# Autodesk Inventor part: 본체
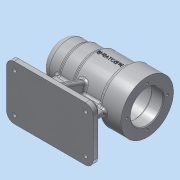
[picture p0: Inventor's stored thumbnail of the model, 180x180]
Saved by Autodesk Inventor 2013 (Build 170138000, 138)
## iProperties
Created: 2016-06
Part Number: 본체
Material: 알루미늄 6061
Document SubType Name: Modeling
Designer: Administrator
Density: 2.71 g/cm^3
Mass: 673.897 g
Surface Area: 647.23 cm^2
Volume: 248.671 cm^3
Author: Administrator
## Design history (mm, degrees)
sketch "스케치1"
  geometry: L1 (-112, 0)-(-112, 25); L2 (-112, 25)-(-87, 25); L3 (-87, 25)-(-87, 27); L4 (-87, 27)-(-67, 27); L5 (-67, 27)-(-67, 30); L6 (-67, 30)-(-28, 30); L7 (-28, 30)-(-28, 34); L8 (-28, 34)-(0, 34); L9 (0, 34)-(0, 0); L10 (0, 0)-(-112, 0)
  constraints: 20 end point, 8 parallel, 1 perpendicular, 1 vertical
  dimensions: "d0" = 50 diameter of L2 L10; "d2" = 54 diameter of L4 L10; "d3" = 60 diameter of L6 L10; "d4" = 68 diameter of L8 L10; "d5" = 25 distance of L1.end L2.end; "d6" = 45 distance between parallel lines of L5 L1; "d7" = 84 distance between parallel lines of L7 L1; "d8" = 112 distance between parallel lines of L9 L1
revolve "회전1" sketch "스케치1" stored, may be unused: angle "d9" = 90 deg
fillet "모깎기1" dims "d10" = 10
fillet "모깎기2" dims "d11" = 3
sketch "스케치2"
  geometry: L1 (-35, -60)-(35, -60); L2 (35, -60)-(35, -70); L3 (35, -70)-(-35, -70); L4 (-35, -70)-(-35, -60); C1 r 34 at (0, 0) reference; 1 further point
  constraints: 8 end point, 2 parallel, 1 horizontal, 1 midpoint, 1 perpendicular, 1 vertical alignment
  dimensions: "d12" = 10 distance of L3.end L1.start; "d14" = 70 distance from line of C1.centre L3; "d15" = 70 distance of L2.end L3.end
extrude "돌출1" join sketch "스케치2" distance "d16" = 112; taper "d17" = 0 deg
sketch "스케치3"
  geometry: L1 (-31, -30)-(-64.804, -30) reference; L2 (-70, -27)-(-85.356, -27) reference; L3 (-89.828, -25)-(-102, -25) reference; L4 (-112, -15)-(-112, 15) reference; L5 (-102, 25)-(-89.828, 25) reference; L6 (-85.356, 27)-(-70, 27) reference; L7 (-64.804, 30)-(-31, 30) reference; L8 (-25.343, 34)-(0, 34) reference; L9 (0, 34)-(0, -34) reference; L10 (0, -34)-(-25.343, -34) reference; L11 (-112, -60)-(0, -60) reference; L12 (0, -60)-(0, -70) reference; L13 (0, -70)-(-112, -70) reference; L14 (-112, -70)-(-112, -60) reference; L15 (-92, -60)-(-92, 0); L16 (-20, -60)-(-20, 0); L17 (-92, 0)-(-20, 0); A1 r 3 centre (-25.343, -31) between (-28.172, -32) and (-25.343, -34) reference; A2 r 3 centre (-31, -33) between (-28.172, -32) and (-31, -30) reference; A3 r 3 centre (-64.804, -27) between (-67.402, -28.5) and (-64.804, -30) reference; A4 r 3 centre (-70, -30) between (-67.402, -28.5) and (-70, -27) reference; A5 r 3 centre (-85.356, -24) between (-87.592, -26) and (-85.356, -27) reference; A6 r 3 centre (-89.828, -28) between (-87.592, -26) and (-89.828, -25) reference; A7 r 10 centre (-102, -15) between (-112, -15) and (-102, -25) reference; A8 r 10 centre (-102, 15) between (-102, 25) and (-112, 15) reference; A9 r 3 centre (-89.828, 28) between (-89.828, 25) and (-87.592, 26) reference; A10 r 3 centre (-85.356, 24) between (-85.356, 27) and (-87.592, 26) reference; A11 r 3 centre (-70, 30) between (-70, 27) and (-67.402, 28.5) reference; A12 r 3 centre (-64.804, 27) between (-64.804, 30) and (-67.402, 28.5) reference; A13 r 3 centre (-31, 33) between (-31, 30) and (-28.172, 32) reference; A14 r 3 centre (-25.343, 31) between (-25.343, 34) and (-28.172, 32) reference; 2 further points
  constraints: 6 end point, 2 parallel, 2 point on line, 1 horizontal alignment, 1 midpoint, 1 perpendicular
  dimensions: "d18" = 20 distance between parallel lines of L12 L16; "d19" = 20 distance between parallel lines of L14 L15
extrude "돌출2" join sketch "스케치3" stored distance "d20" = 8; taper "d21" = 0 deg
node "작업 평면1"
sketch "스케치4"
  geometry: L1 (-35, -70)-(-35, -60) reference; L2 (-35, -60)-(-4, -60) reference; L3 (-4, -60)-(-4, -29.732) reference; L4 (4, -29.732)-(4, -60) reference; L5 (4, -60)-(35, -60) reference; L6 (35, -60)-(35, -70) reference; L7 (35, -70)-(-35, -70) reference; L8 (28, -60)-(6.162, 0); L9 (-28, -60)-(-6.162, 0); L10 (-6.162, 0)-(6.162, 0); A1 r 30 centre (0, 0) between (4, -29.732) and (-4, -29.732) reference; 1 further point
  constraints: 6 end point, 2 horizontal alignment, 2 point on line, 1 parallel
  dimensions: "d23" = 110 deg angle of L5 L8; "d24" = 110 deg angle of L2 L9; "d25" = 7 distance from line of L9.start L1; "d26" = 7 distance from line of L6 L8.start
extrude "돌출3" join sketch "스케치4" stored distance "d27" = 8; taper "d28" = 0 deg
sketch "스케치5"
  geometry: L1 (0, 26)-(0, -26); L2 (-26, 0)-(26, 0); C1 r 34 at (0, 0) reference; 5 further points
  constraints: 5 coincident, 4 end point, 2 midpoint, 2 perpendicular, 1 vertical
  dimensions: "d29" = 52 distance of L2.start L2.end
hole "구멍1" sketch "스케치5" at (0, 26), (-26, 0), (0, -26), (26, 0) diameter "d31" = 3.242; stored, may be unused: countersink angle "d35" = 90 deg, drill point angle "d37" = 118 deg; dims "d32" = 8, "d33" = 4, "d34" = 2, "d36" = 11
sketch "스케치6"
  geometry: L1 (0, 70)-(-112, 70) reference; L2 (-112, 0)-(-112, 70) reference; L3 (-102, 60)-(-10, 60); L4 (-10, 60)-(-10, 10); L5 (-10, 10)-(-102, 10); L6 (-102, 10)-(-102, 60); 9 further points
  constraints: 8 end point, 4 coincident, 4 midpoint, 2 parallel, 1 horizontal, 1 horizontal alignment, 1 perpendicular, 1 vertical alignment
  dimensions: "d38" = 92 distance of L4.end L5.end; "d40" = 50 distance of L5.end L3.start
hole "구멍2" sketch "스케치6" at (-102, 60), (-10, 60), (-102, 10), (-10, 10) diameter "d41" = 5; stored, may be unused: countersink angle "d45" = 90 deg, drill point angle "d47" = 118 deg; dims "d42" = 5, "d43" = 9, "d44" = 4, "d46" = 11
node "작업 평면2"
sketch "스케치7"
  geometry: L1 (0, -34)-(0, 34) reference; 3 further points
  constraints: 1 horizontal alignment, 1 midpoint, 1 other
  dimensions: "d49" = 48 distance from line of L1 point (-48, 0)
feature "엠보싱1" sketch "스케치7" dims "d50" = 0.5, "d51" = 0
fillet "모깎기3" dims "d52" = 10
sketch "스케치8"
  geometry: L1 (-25.343, 34)-(0, 34) reference; L2 (0, 34)-(0, 27.621) reference; L3 (0, 27.621)-(-11, 27.621) reference; L4 (-11, 27.621)-(-11.974, 26) reference; L5 (-11.974, 26)-(-11, 24.379) reference; L6 (-11, 24.379)-(0, 24.379) reference; L7 (0, 24.379)-(0, -24.379) reference; L8 (0, -24.379)-(-11, -24.379) reference; L9 (-11, -24.379)-(-11.974, -26) reference; L10 (-11.974, -26)-(-11, -27.621) reference; L11 (-11, -27.621)-(0, -27.621) reference; L12 (0, -27.621)-(0, -34) reference; L13 (0, -34)-(-20, -34) reference; L14 (-20, -34)-(-20, -60) reference; L15 (-20, -60)-(0, -60) reference; L16 (0, -60)-(0, -70) reference; L17 (0, -70)-(-112, -70) reference; L18 (-112, -70)-(-112, -60) reference; L19 (-112, -60)-(-92, -60) reference; L20 (-92, -60)-(-92, -25) reference; L21 (-92, -25)-(-102, -25) reference; L22 (-112, -15)-(-112, 15) reference; L23 (-102, 25)-(-89.828, 25) reference; L24 (-85.356, 27)-(-70, 27) reference; L25 (-64.804, 30)-(-31, 30) reference; L26 (-106, 0)-(-106, 10.5); L27 (-106, 10.5)-(-103, 10.5); L28 (-103, 10.5)-(-103, 16); L29 (-103, 16)-(-99, 16); L30 (-99, 16)-(-99, 17.5); L31 (-99, 17.5)-(-81, 17.5); L32 (-81, 17.5)-(-81, 21); L33 (-81, 21)-(-69, 21); L34 (-69, 21)-(-69, 24); L35 (-69, 24)-(-15, 24); L36 (-15, 24)-(-15, 21); L37 (-15, 21)-(0, 21); L38 (-106, 0)-(0, 0); A1 r 3 centre (-25.343, 31) between (-25.343, 34) and (-28.172, 32) reference; A2 r 10 centre (-102, -15) between (-112, -15) and (-102, -25) reference; A3 r 10 centre (-102, 15) between (-102, 25) and (-112, 15) reference; A4 r 3 centre (-89.828, 28) between (-89.828, 25) and (-87.592, 26) reference; A5 r 3 centre (-85.356, 24) between (-85.356, 27) and (-87.592, 26) reference; A6 r 3 centre (-70, 30) between (-70, 27) and (-67.402, 28.5) reference; A7 r 3 centre (-64.804, 27) between (-64.804, 30) and (-67.402, 28.5) reference; A8 r 3 centre (-31, 33) between (-31, 30) and (-28.172, 32) reference
  constraints: 26 end point, 8 parallel, 5 perpendicular, 1 point on line
  dimensions: "d53" = 3 distance of L26.end L27.end; "d55" = 4 distance of L28.end L29.end; "d56" = 18 distance of L30.end L31.end; "d57" = 12 distance of L32.end L33.end; "d58" = 54 distance of L34.end L35.end; "d59" = 15 distance of L36.end L37.end; "d60" = 42 diameter of L37 L38; "d61" = 48 diameter of L35 L38; "d62" = 42 diameter of L33 L38; "d63" = 35 diameter of L31 L38; "d64" = 32 diameter of L29 L38; "d65" = 21 diameter of L27 L38
revolve "회전2" sketch "스케치8" stored, may be unused: angle "d66" = 90 deg
fillet "모깎기4" dims "d67" = 3
fillet "모깎기5" dims "d68" = 0.3
fillet "모깎기6" dims "d69" = 3
chamfer "모따기1" distance "d70" = 1; stored, may be unused: second distance "d71" = 2, angle "d72" = 45 deg
fillet "모깎기7" dims "d73" = 3
fillet "모깎기9" dims "d75" = 3
chamfer "모따기2" distance "d76" = 4; stored, may be unused: second distance "d77" = 2, angle "d78" = 45 deg
node "솔리드1"
node "절단 모서리 투영1"
node "절단 모서리 투영2"
node "절단 모서리 투영3"
other parameters: "d48" = 98.75
